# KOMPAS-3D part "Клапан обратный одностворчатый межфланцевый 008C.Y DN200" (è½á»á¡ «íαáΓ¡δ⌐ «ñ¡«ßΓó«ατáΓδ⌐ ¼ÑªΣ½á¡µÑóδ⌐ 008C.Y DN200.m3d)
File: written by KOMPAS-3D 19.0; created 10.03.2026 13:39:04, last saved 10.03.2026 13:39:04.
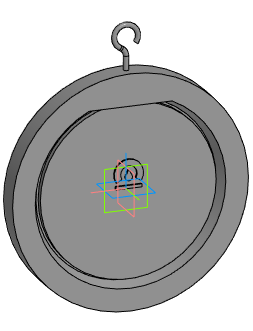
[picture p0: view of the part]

Document properties: Автор: Евгений; Полное имя файла: E:\Dendor\3D для проектировщиков\5.1 Тип 008C. Клапан обратный одностворчатый межфланцевый\stp_Клапан обратный одностворчатый межфланцевый 008C.Y\Клапан обратный одностворчатый межфланцевый 008C.Y DN200.m3d

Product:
- Part/product: Клапан обратный одностворчатый межфланцевый 008C.Y DN200

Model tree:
1. Операция без истории:1  (labels: Клапан обратный одностворчатый межфланцевый 008C.Y DN200)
